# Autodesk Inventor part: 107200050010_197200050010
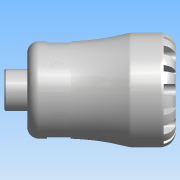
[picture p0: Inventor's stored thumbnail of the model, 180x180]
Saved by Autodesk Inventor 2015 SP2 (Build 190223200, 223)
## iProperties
Created: 2016-12
Part Number: 107200050010_197200050010
Material: PVC-Piping
Description: PLASSON MALE INTEGRAL BRASS THREAD 50X1" SERIES 1
Document SubType Name: Modeling
Designer: KIM
Mass: 61.7504 g
Surface Area: 140.097 cm^2
Volume: 44.1074 cm^3
Density: 1.4 g/cm^3
Appearance: Smooth - White
Author: KIM
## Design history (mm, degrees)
derived "1072.ipt"
feature "Solid1::1072.ipt"
tag "TaggingFeature1"
body "Solid1"
other parameters: "d0" = 127, "d1" = 34.02, "d3" = 62.5, "d4" = 85, "d6" = 81, "d8" = 72.25, "d13" = 9, "d14" = 9, "d15" = 0, "d17" = 360 deg, "d19" = 8 deg, "d20" = 1, "d21" = 1, "d22" = 8 deg, "d24" = 0, "d26" = 360 deg, "d32" = 8.5, "d33" = 8.5, "d34" = 30.931, "d38" = 17, "d39" = 0.92793, "d42" = 17.5, "d43" = 11.5, "d45" = 17.64, "d46" = 0, "d59" = 360 deg, "d61" = 14.875, "d62" = 1, "d64" = 0, "d65" = 0.85, "d68" = 7.14286, "E_" = 85, "H_" = 127, "l_" = 81, "R_" = 30.931, "l_2" = 17, "d9" = 11.25, "d11" = 85, "d12" = 62.5
